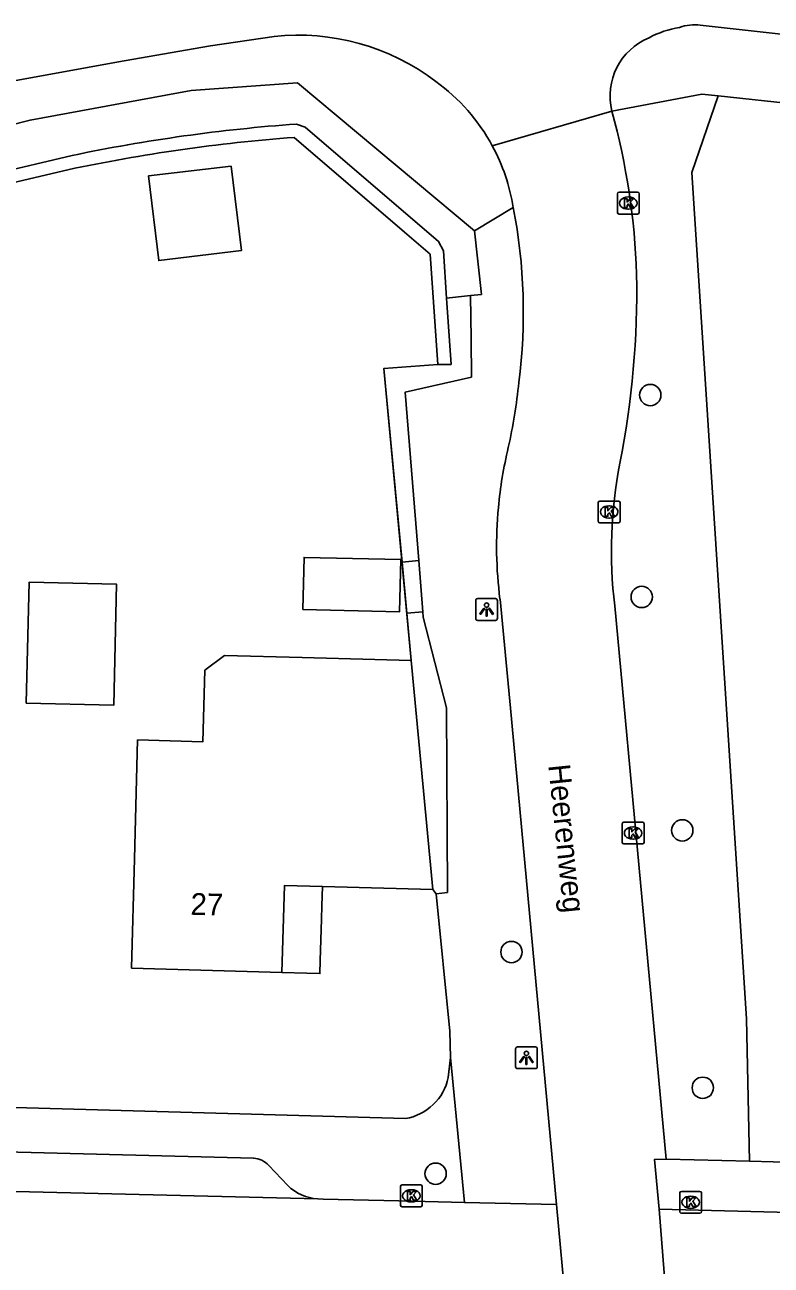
# Model space of a CAD drawing. Extents: x 162082 to 163393, y 388091 to 388632.
# Drawn here: x 162508.1 to 162542.3, y 388533.9 to 388590.7 of the extents above; entities that cross this region are included whole.
import ezdxf

# ---------------------------------------------------------------- set-up
doc = ezdxf.new("R2010")
doc.units = 0
for name, color, linetype in [('IMGEO_Berm_groen', 7, 'Continuous'), ('IMGEO_Boom', 7, 'Continuous'), ('IMGEO_Fietspad_gesloten', 7, 'Continuous'), ('IMGEO_Groenvoorziening', 7, 'Continuous'), ('IMGEO_Kolk', 7, 'Continuous'), ('IMGEO_Lichtpunt', 7, 'Continuous'), ('IMGEO_Muur', 7, 'Continuous'), ('IMGEO_Openbare_ruimte_label', 7, 'Continuous'), ('IMGEO_Pand', 7, 'Continuous'), ('IMGEO_Pand_nummerreeks', 7, 'Continuous'), ('IMGEO_Pand_overbouw', 7, 'Continuous'), ('IMGEO_Rijbaan_lokaal_open', 7, 'Continuous'), ('IMGEO_Voetpad_open', 7, 'Continuous')]:
    doc.layers.add(name, color=color, linetype=linetype)

msp = doc.modelspace()

# ---------------------------------------------------------------- linework, layer by layer
at = {"layer": 'IMGEO_Berm_groen'}
msp.add_lwpolyline([(162528.501, 388578.326), (162527.4, 388578.214)], dxfattribs=at)
at = {"layer": 'IMGEO_Boom'}
for centre in [(162536.728, 388573.768), (162536.338, 388564.521), (162538.194, 388553.825), (162530.371, 388548.256), (162539.133, 388542.036), (162526.896, 388538.102)]:
    msp.add_circle(centre, 0.489, dxfattribs=at)
at = {"layer": 'IMGEO_Fietspad_gesloten'}
for points in [[(162544.501, 388590.106), (162539.018, 388590.709)], [(162519.496, 388590.2), (162516.59, 388589.758), (162512.632, 388589.073), (162509.682, 388588.537), (162505.734, 388587.824)], [(162534.972, 388586.774), (162529.493, 388585.182)], [(162529.845, 388564.412), (162530.321, 388559.432), (162532.438, 388536.687)], [(162537.451, 388538.768), (162535.099, 388564.112)], [(162537.127, 388536.469), (162536.924, 388538.758), (162537.451, 388538.768)]]:
    msp.add_lwpolyline(points, dxfattribs=at)
for centre, radius, start, end in [((162538.743, 388588.765), 1.964, 81.9389, 109.9972), ((162520.589, 388579.802), 10.455, 52.7999, 96.0004), ((162537.771, 388587.468), 2.884, 112.4426, 193.9235), ((162538.777, 388586.241), 4.426, 99.1772, 118.4272), ((162521.72, 388580.977), 8.837, 28.4121, 54.0367), ((162503.529, 388578.194), 32.593, 1.9418, 15.2636), ((162521.726, 388580.972), 8.835, 9.0316, 28.4582), ((162505.706, 388577.557), 25.207, 352.6935, 10.9828), ((162495.209, 388578.553), 40.901, 348.8518, 1.0436), ((162504.454, 388577.051), 26.392, 347.5513, 354.1276), ((162548.826, 388566.863), 19.136, 166.4025, 174.7473), ((162556.072, 388566.616), 21.122, 169.0024, 186.8073), ((162549, 388566.856), 19.311, 174.7737, 187.2709)]:
    msp.add_arc(centre, radius, start, end, dxfattribs=at)
at = {"layer": 'IMGEO_Groenvoorziening'}
for points in [[(162541.269, 388538.669), (162541.135, 388545.2), (162538.637, 388583.97), (162539.844, 388587.475)], [(162525.358, 388566.116), (162524.526, 388574.989), (162526.996, 388575.161)], [(162525.78, 388561.61), (162525.576, 388563.783)], [(162526.927, 388550.918), (162526.77, 388551.12)]]:
    msp.add_lwpolyline(points, dxfattribs=at)
at = {"layer": 'IMGEO_Kolk'}
for p, q in [((162535.22, 388582.136), (162535.22, 388582.988)), ((162535.295, 388583.062), (162536.147, 388583.062)), ((162535.708, 388582.842), (162535.733, 388582.842)), ((162536.221, 388582.988), (162536.221, 388582.136)), ((162535.731, 388582.282), (162535.706, 388582.282)), ((162536.147, 388582.062), (162535.295, 388582.062)), ((162534.345, 388567.989), (162534.345, 388568.841)), ((162534.42, 388568.915), (162535.272, 388568.915)), ((162534.833, 388568.695), (162534.858, 388568.695)), ((162535.346, 388568.841), (162535.346, 388567.989)), ((162534.856, 388568.135), (162534.831, 388568.135)), ((162535.272, 388567.915), (162534.42, 388567.915)), ((162535.441, 388553.279), (162535.441, 388554.131)), ((162535.516, 388554.205), (162536.368, 388554.205)), ((162535.929, 388553.985), (162535.954, 388553.985)), ((162536.442, 388554.131), (162536.442, 388553.279)), ((162536.368, 388553.205), (162535.516, 388553.205)), ((162535.952, 388553.425), (162535.927, 388553.425)), ((162525.286, 388536.661), (162525.286, 388537.513)), ((162525.361, 388537.587), (162526.213, 388537.587)), ((162525.774, 388537.367), (162525.799, 388537.367)), ((162526.287, 388537.513), (162526.287, 388536.661)), ((162538.152, 388537.293), (162539.004, 388537.293)), ((162525.797, 388536.807), (162525.772, 388536.807)), ((162538.077, 388536.367), (162538.077, 388537.219)), ((162538.565, 388537.073), (162538.59, 388537.073)), ((162539.078, 388537.219), (162539.078, 388536.367)), ((162526.213, 388536.587), (162525.361, 388536.587)), ((162539.004, 388536.293), (162538.152, 388536.293)), ((162538.588, 388536.513), (162538.563, 388536.513))]:
    msp.add_line(p, q, dxfattribs=at)
for points in [[(162535.22, 388582.136), (162535.22, 388582.988)], [(162535.295, 388583.062), (162536.147, 388583.062)], [(162535.541, 388582.762), (162535.664, 388582.762), (162535.664, 388582.611), (162535.794, 388582.762), (162535.958, 388582.762), (162535.812, 388582.611), (162535.965, 388582.362), (162535.813, 388582.362), (162535.728, 388582.526), (162535.664, 388582.459), (162535.664, 388582.362), (162535.541, 388582.362), (162535.541, 388582.762)], [(162536.221, 388582.988), (162536.221, 388582.136)], [(162536.147, 388582.062), (162535.295, 388582.062)], [(162534.345, 388567.989), (162534.345, 388568.841)], [(162534.42, 388568.915), (162535.272, 388568.915)], [(162534.666, 388568.615), (162534.789, 388568.615), (162534.789, 388568.464), (162534.919, 388568.615), (162535.083, 388568.615), (162534.937, 388568.464), (162535.09, 388568.215), (162534.938, 388568.215), (162534.853, 388568.379), (162534.789, 388568.312), (162534.789, 388568.215), (162534.666, 388568.215), (162534.666, 388568.615)], [(162535.346, 388568.841), (162535.346, 388567.989)], [(162535.272, 388567.915), (162534.42, 388567.915)], [(162535.441, 388553.279), (162535.441, 388554.131)], [(162535.516, 388554.205), (162536.368, 388554.205)], [(162535.762, 388553.905), (162535.885, 388553.905), (162535.885, 388553.754), (162536.015, 388553.905), (162536.179, 388553.905), (162536.033, 388553.754), (162536.186, 388553.505), (162536.034, 388553.505), (162535.949, 388553.669), (162535.885, 388553.602), (162535.885, 388553.505), (162535.762, 388553.505), (162535.762, 388553.905)], [(162536.442, 388554.131), (162536.442, 388553.279)], [(162536.368, 388553.205), (162535.516, 388553.205)], [(162525.286, 388536.661), (162525.286, 388537.513)], [(162525.361, 388537.587), (162526.213, 388537.587)], [(162525.607, 388537.287), (162525.73, 388537.287), (162525.73, 388537.136), (162525.86, 388537.287), (162526.024, 388537.287), (162525.878, 388537.136), (162526.031, 388536.887), (162525.879, 388536.887), (162525.794, 388537.051), (162525.73, 388536.984), (162525.73, 388536.887), (162525.607, 388536.887), (162525.607, 388537.287)], [(162526.287, 388537.513), (162526.287, 388536.661)], [(162538.152, 388537.293), (162539.004, 388537.293)], [(162538.077, 388536.367), (162538.077, 388537.219)], [(162538.398, 388536.993), (162538.521, 388536.993), (162538.521, 388536.842), (162538.651, 388536.993), (162538.815, 388536.993), (162538.669, 388536.842), (162538.822, 388536.593), (162538.67, 388536.593), (162538.585, 388536.757), (162538.521, 388536.69), (162538.521, 388536.593), (162538.398, 388536.593), (162538.398, 388536.993)], [(162539.078, 388537.219), (162539.078, 388536.367)], [(162526.213, 388536.587), (162525.361, 388536.587)], [(162539.004, 388536.293), (162538.152, 388536.293)]]:
    msp.add_lwpolyline(points, dxfattribs=at)
for centre, start, end in [((162535.297, 388582.986), 91.552, 178.448), ((162535.297, 388582.986), 91.552, 178.448), ((162536.145, 388582.986), 1.552, 88.448), ((162536.145, 388582.986), 1.552, 88.448), ((162535.297, 388582.138), 181.552, 268.448), ((162535.297, 388582.138), 181.552, 268.448), ((162536.145, 388582.138), 271.552, 358.448), ((162536.145, 388582.138), 271.552, 358.448), ((162534.422, 388568.839), 91.552, 178.448), ((162534.422, 388568.839), 91.552, 178.448), ((162535.27, 388568.839), 1.552, 88.448), ((162535.27, 388568.839), 1.552, 88.448), ((162534.422, 388567.991), 181.552, 268.448), ((162534.422, 388567.991), 181.552, 268.448), ((162535.27, 388567.991), 271.552, 358.448), ((162535.27, 388567.991), 271.552, 358.448), ((162535.518, 388554.129), 91.552, 178.448), ((162535.518, 388554.129), 91.552, 178.448), ((162536.366, 388554.129), 1.552, 88.448), ((162536.366, 388554.129), 1.552, 88.448), ((162535.518, 388553.281), 181.552, 268.448), ((162535.518, 388553.281), 181.552, 268.448), ((162536.366, 388553.281), 271.552, 358.448), ((162536.366, 388553.281), 271.552, 358.448), ((162525.363, 388537.511), 91.552, 178.448), ((162525.363, 388537.511), 91.552, 178.448), ((162526.211, 388537.511), 1.552, 88.448), ((162526.211, 388537.511), 1.552, 88.448), ((162538.154, 388537.217), 91.552, 178.448), ((162538.154, 388537.217), 91.552, 178.448), ((162539.002, 388537.217), 1.552, 88.448), ((162539.002, 388537.217), 1.552, 88.448), ((162525.363, 388536.663), 181.552, 268.448), ((162525.363, 388536.663), 181.552, 268.448), ((162526.211, 388536.663), 271.552, 358.448), ((162526.211, 388536.663), 271.552, 358.448), ((162538.154, 388536.369), 181.552, 268.448), ((162538.154, 388536.369), 181.552, 268.448), ((162539.002, 388536.369), 271.552, 358.448), ((162539.002, 388536.369), 271.552, 358.448)]:
    msp.add_arc(centre, 0.0765, start, end, dxfattribs=at)
for centre, major_axis, ratio, start_param, end_param in [((162535.707, 388582.562), (-0.387, 0.002), 0.722429, 4.712389, 7.853982), ((162535.732, 388582.562), (-0.39, 0.002), 0.717154, 1.570796, 4.712389), ((162534.832, 388568.415), (-0.387, 0.002), 0.722429, 4.712389, 7.853982), ((162534.857, 388568.415), (-0.39, 0.002), 0.717154, 1.570796, 4.712389), ((162535.928, 388553.705), (-0.387, 0.002), 0.722429, 4.712389, 7.853982), ((162535.953, 388553.705), (-0.39, 0.002), 0.717154, 1.570796, 4.712389), ((162525.773, 388537.087), (-0.387, 0.002), 0.722429, 4.712389, 7.853982), ((162525.798, 388537.087), (-0.39, 0.002), 0.717154, 1.570796, 4.712389), ((162538.564, 388536.793), (-0.387, 0.002), 0.722429, 4.712389, 7.853982), ((162538.589, 388536.793), (-0.39, 0.002), 0.717154, 1.570796, 4.712389)]:
    msp.add_ellipse(centre, major_axis=major_axis, ratio=ratio, start_param=start_param, end_param=end_param, dxfattribs=at)
at = {"layer": 'IMGEO_Lichtpunt'}
for p, q in [((162528.733, 388564.349), (162528.733, 388563.542)), ((162528.733, 388564.349), (162528.733, 388563.542)), ((162529.635, 388564.444), (162528.827, 388564.444)), ((162529.635, 388564.444), (162528.827, 388564.444)), ((162529.729, 388563.542), (162529.729, 388564.349)), ((162529.729, 388563.542), (162529.729, 388564.349)), ((162528.827, 388563.448), (162529.635, 388563.448)), ((162528.827, 388563.448), (162529.635, 388563.448)), ((162530.557, 388543.815), (162530.557, 388543.008)), ((162530.557, 388543.815), (162530.557, 388543.008)), ((162531.459, 388543.91), (162530.651, 388543.91)), ((162531.459, 388543.91), (162530.651, 388543.91)), ((162531.553, 388543.008), (162531.553, 388543.815)), ((162531.553, 388543.008), (162531.553, 388543.815)), ((162530.651, 388542.914), (162531.459, 388542.914)), ((162530.651, 388542.914), (162531.459, 388542.914))]:
    msp.add_line(p, q, dxfattribs=at)
for points in [[(162529.107, 388564.013), (162529.146, 388563.985), (162528.958, 388563.723), (162528.92, 388563.75), (162529.107, 388564.013)], [(162529.319, 388563.985), (162529.357, 388564.012), (162529.544, 388563.75), (162529.505, 388563.722), (162529.319, 388563.985)], [(162529.209, 388563.965), (162529.256, 388563.965), (162529.256, 388563.643), (162529.209, 388563.643), (162529.209, 388563.965)], [(162530.931, 388543.479), (162530.97, 388543.451), (162530.782, 388543.189), (162530.744, 388543.216), (162530.931, 388543.479)], [(162531.033, 388543.431), (162531.08, 388543.431), (162531.08, 388543.109), (162531.033, 388543.109), (162531.033, 388543.431)], [(162531.143, 388543.451), (162531.181, 388543.478), (162531.368, 388543.216), (162531.329, 388543.188), (162531.143, 388543.451)]]:
    msp.add_lwpolyline(points, dxfattribs=at)
for centre in [(162529.232, 388564.147), (162531.056, 388543.613)]:
    msp.add_circle(centre, 0.0994, dxfattribs=at)
for centre, start, end in [((162528.827, 388564.349), 90, 180), ((162528.827, 388564.349), 90, 180), ((162529.635, 388564.349), 0, 90), ((162529.635, 388564.349), 0, 90), ((162528.827, 388563.542), 180, 270), ((162528.827, 388563.542), 180, 270), ((162529.635, 388563.542), 270, 0), ((162529.635, 388563.542), 270, 360), ((162530.651, 388543.815), 90, 180), ((162530.651, 388543.815), 90, 180), ((162531.459, 388543.815), 0, 90), ((162531.459, 388543.815), 0, 90), ((162530.651, 388543.008), 180, 270), ((162530.651, 388543.008), 180, 270), ((162531.459, 388543.008), 270, 0), ((162531.459, 388543.008), 270, 360)]:
    msp.add_arc(centre, 0.0946, start, end, dxfattribs=at)
at = {"layer": 'IMGEO_Muur'}
for points in [[(162527.4, 388578.214), (162527.255, 388580.37), (162527.032, 388580.803), (162520.922, 388586.037), (162520.527, 388586.182)], [(162526.996, 388575.161), (162526.652, 388580.215), (162525.471, 388581.23), (162520.42, 388585.572)], [(162510.249, 388584.742), (162506.611, 388583.883), (162500, 388581.823), (162413.144, 388552.843), (162413.523, 388551.803), (162288.31, 388509.989), (162287.972, 388511.055), (162273.962, 388506.386)], [(162510.057, 388584.088), (162506.73, 388583.313), (162500, 388581.185), (162447.072, 388563.529), (162443.929, 388562.48)], [(162526.996, 388575.161), (162527.604, 388575.175), (162527.4, 388578.214)], [(162524.526, 388574.989), (162525.78, 388561.61)]]:
    msp.add_lwpolyline(points, dxfattribs=at)
for centre, radius, start, end in [((162526.011, 388509.637), 76.741, 94.09823, 101.8528), ((162526.085, 388509.086), 76.695, 94.23605, 102.06285)]:
    msp.add_arc(centre, radius, start, end, dxfattribs=at)
at = {"layer": 'IMGEO_Pand'}
for points in [[(162517.537, 388584.258), (162513.753, 388583.805), (162514.217, 388579.931), (162518.001, 388580.385), (162517.537, 388584.258)], [(162520.816, 388563.943), (162520.869, 388566.332), (162525.299, 388566.232), (162525.246, 388563.843), (162520.816, 388563.943)], [(162508.15, 388559.66), (162508.274, 388565.194), (162512.283, 388565.104), (162512.159, 388559.57), (162508.15, 388559.66)], [(162526.77, 388551.12), (162521.714, 388551.254), (162519.97, 388551.3), (162519.86, 388547.32), (162512.97, 388547.52), (162513.104, 388552.519), (162513.25, 388557.97), (162516.24, 388557.89), (162516.33, 388561.16), (162517.22, 388561.84), (162520.782, 388561.744), (162525.78, 388561.61)], [(162525.78, 388561.61), (162526.77, 388551.12)]]:
    msp.add_lwpolyline(points, dxfattribs=at)
at = {"layer": 'IMGEO_Pand_overbouw'}
msp.add_lwpolyline([(162521.714, 388551.254), (162519.97, 388551.3), (162519.86, 388547.32), (162520.997, 388547.288), (162521.597, 388547.267), (162521.615, 388547.868), (162521.671, 388549.766), (162521.688, 388550.366)], close=True, dxfattribs=at)
at = {"layer": 'IMGEO_Rijbaan_lokaal_open'}
for points in [[(162456.709, 388538.522), (162521.496, 388536.948)], [(162528.218, 388536.787), (162525.212, 388536.859), (162521.744, 388536.942), (162521.496, 388536.948)], [(162528.218, 388536.787), (162532.438, 388536.687)], [(162532.438, 388536.687), (162532.881, 388531.889)], [(162537.127, 388536.469), (162545.528, 388536.263)], [(162537.535, 388531.429), (162537.127, 388536.469)]]:
    msp.add_lwpolyline(points, dxfattribs=at)
at = {"layer": 'IMGEO_Voetpad_open'}
for points in [[(162273.962, 388506.386), (162273.308, 388508.352), (162359.569, 388536.999), (162408.33, 388553.192), (162500, 388583.748), (162506.331, 388585.858), (162508.323, 388586.366), (162515.7, 388587.719), (162520.573, 388588.069), (162528.682, 388581.286)], [(162534.972, 388586.774), (162539.096, 388587.558), (162539.844, 388587.475)], [(162539.844, 388587.475), (162543.513, 388587.071)], [(162528.682, 388581.286), (162530.451, 388582.359)], [(162528.682, 388581.286), (162528.996, 388578.377), (162528.501, 388578.326)], [(162526.126, 388566.183), (162525.506, 388573.902), (162528.532, 388574.588), (162528.517, 388576.343), (162528.501, 388578.326)], [(162526.126, 388566.183), (162525.358, 388566.116)], [(162525.576, 388563.783), (162525.358, 388566.116)], [(162526.311, 388563.836), (162526.126, 388566.183)], [(162526.311, 388563.836), (162525.576, 388563.783)], [(162526.927, 388550.918), (162527.438, 388550.987), (162527.391, 388559.444), (162526.328, 388563.592), (162526.311, 388563.836)], [(162527.572, 388543.417), (162527.54, 388544.624), (162526.927, 388550.918)], [(162527.474, 388542.512), (162527.572, 388543.417)], [(162527.572, 388543.417), (162528.218, 388536.787)], [(162446.71, 388539.251), (162451.096, 388540.559), (162452.514, 388540.663), (162453.787, 388540.666), (162453.829, 388542.464), (162500, 388541.354), (162525.515, 388540.624)], [(162518.563, 388538.816), (162507.162, 388539.099), (162503.799, 388539.182), (162489.573, 388539.534), (162485.933, 388539.624), (162473.509, 388539.932), (162467.811, 388540.073), (162459.579, 388540.277)], [(162541.269, 388538.669), (162545.611, 388538.556), (162545.696, 388540.38)], [(162520.128, 388537.554), (162519.255, 388538.483)], [(162537.451, 388538.768), (162537.463, 388538.768), (162541.269, 388538.669)]]:
    msp.add_lwpolyline(points, dxfattribs=at)
for centre, radius, start, end in [((162525.115, 388542.999), 2.409, 279.5606, 348.3248), ((162518.478, 388537.753), 1.066, 43.188, 85.417), ((162521.649, 388539.141), 2.199, 226.2157, 265.9992)]:
    msp.add_arc(centre, radius, start, end, dxfattribs=at)

# ---------------------------------------------------------------- texts
at = {"layer": 'IMGEO_Openbare_ruimte_label'}
msp.add_text('Heerenweg', height=1, rotation=275.9101, dxfattribs=at).set_placement((162532.051, 388556.813))
at = {"layer": 'IMGEO_Pand_nummerreeks'}
msp.add_text('27', height=1, rotation=358.3373, dxfattribs=at).set_placement((162515.662, 388549.963))

doc.saveas('drawing.dxf')
